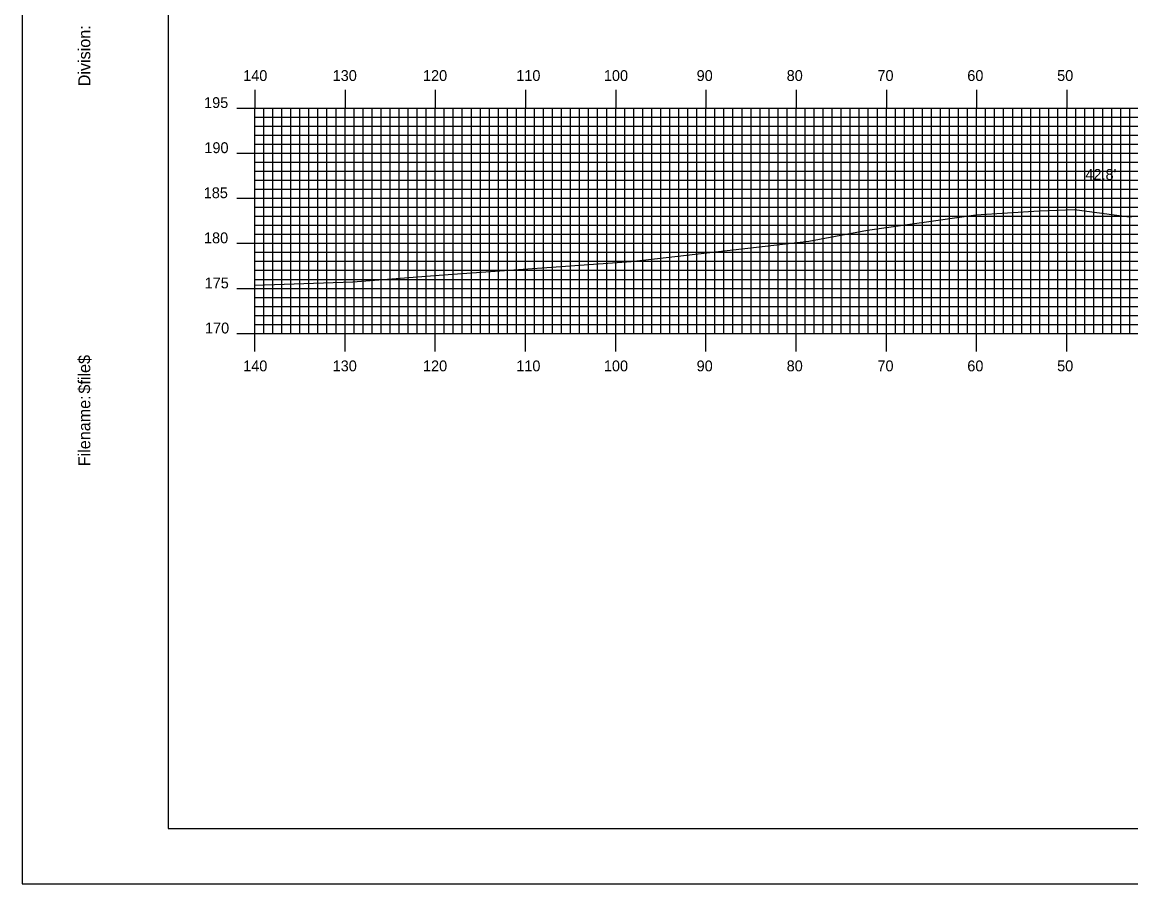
# Model space of a CAD drawing. Extents: x 1823966 to 1824309, y 442591 to 442811.
# Drawn here: x 1823966 to 1824088.9, y 442590.5 to 442686.1 of the extents above; entities that cross this region are included whole.
import ezdxf

# ---------------------------------------------------------------- set-up
doc = ezdxf.new("R2010")
doc.units = 0
for name, color, linetype in [('BORDER', 7, 'Continuous'), ('D_Text_Standard', 7, 'Continuous'), ('H_V ANNOTATION', 7, 'Continuous'), ('MAJOR', 7, 'Continuous'), ('MINOR', 7, 'Continuous'), ('PLOT BOUNDARY', 7, 'Continuous'), ('S_Roadway_Centerline', 7, 'Continuous')]:
    doc.layers.add(name, color=color, linetype=linetype)

msp = doc.modelspace()

# ---------------------------------------------------------------- linework, layer by layer
at = {"layer": 'BORDER'}
msp.add_lwpolyline([(1823982.22, 442596.67), (1824302.22, 442596.67), (1824302.22, 442806.67), (1823982.22, 442806.67)], close=True, dxfattribs=at)
at = {"layer": 'MAJOR'}
for p, q in [((1823991.82, 442678.59), (1823991.82, 442676.59)), ((1824001.82, 442678.59), (1824001.82, 442676.59)), ((1824011.82, 442678.59), (1824011.82, 442676.59)), ((1824021.82, 442678.59), (1824021.82, 442676.59)), ((1824031.82, 442678.59), (1824031.82, 442676.59)), ((1824041.82, 442678.59), (1824041.82, 442676.59)), ((1824051.82, 442678.59), (1824051.82, 442676.59)), ((1824061.82, 442678.59), (1824061.82, 442676.59)), ((1824071.82, 442678.59), (1824071.82, 442676.59)), ((1824081.82, 442678.59), (1824081.82, 442676.59)), ((1823989.82, 442676.59), (1823991.82, 442676.59)), ((1823991.82, 442676.59), (1824271.82, 442676.59)), ((1823991.82, 442651.59), (1823991.82, 442676.59)), ((1823991.82, 442651.59), (1823991.82, 442676.59)), ((1823991.82, 442676.59), (1824271.82, 442676.59)), ((1824001.82, 442651.59), (1824001.82, 442676.59)), ((1824011.82, 442651.59), (1824011.82, 442676.59)), ((1824021.82, 442651.59), (1824021.82, 442676.59)), ((1824031.82, 442651.59), (1824031.82, 442676.59)), ((1824041.82, 442651.59), (1824041.82, 442676.59)), ((1824051.82, 442651.59), (1824051.82, 442676.59)), ((1824061.82, 442651.59), (1824061.82, 442676.59)), ((1824071.82, 442651.59), (1824071.82, 442676.59)), ((1824081.82, 442651.59), (1824081.82, 442676.59)), ((1823989.82, 442671.59), (1823991.82, 442671.59)), ((1823991.82, 442671.59), (1824271.82, 442671.59)), ((1823989.82, 442666.59), (1823991.82, 442666.59)), ((1823991.82, 442666.59), (1824271.82, 442666.59)), ((1823989.82, 442661.59), (1823991.82, 442661.59)), ((1823991.82, 442661.59), (1824271.82, 442661.59)), ((1823989.82, 442656.59), (1823991.82, 442656.59)), ((1823991.82, 442656.59), (1824271.82, 442656.59)), ((1823989.82, 442651.59), (1823991.82, 442651.59)), ((1823991.82, 442651.59), (1824271.82, 442651.59)), ((1823991.82, 442651.59), (1824271.82, 442651.59)), ((1823991.82, 442649.58), (1823991.82, 442651.59)), ((1824001.82, 442649.58), (1824001.82, 442651.59)), ((1824011.82, 442649.58), (1824011.82, 442651.59)), ((1824021.82, 442649.58), (1824021.82, 442651.59)), ((1824031.82, 442649.58), (1824031.82, 442651.59)), ((1824041.82, 442649.58), (1824041.82, 442651.59)), ((1824051.82, 442649.58), (1824051.82, 442651.59)), ((1824061.82, 442649.58), (1824061.82, 442651.59)), ((1824071.82, 442649.58), (1824071.82, 442651.59)), ((1824081.82, 442649.58), (1824081.82, 442651.59))]:
    msp.add_line(p, q, dxfattribs=at)
at = {"layer": 'MINOR'}
for p, q in [((1823992.82, 442651.59), (1823992.82, 442676.59)), ((1823993.82, 442651.59), (1823993.82, 442676.59)), ((1823994.82, 442651.59), (1823994.82, 442676.59)), ((1823995.82, 442651.59), (1823995.82, 442676.59)), ((1823996.82, 442651.59), (1823996.82, 442676.59)), ((1823997.82, 442651.59), (1823997.82, 442676.59)), ((1823998.82, 442651.59), (1823998.82, 442676.59)), ((1823999.82, 442651.59), (1823999.82, 442676.59)), ((1824000.82, 442651.59), (1824000.82, 442676.59)), ((1824002.82, 442651.59), (1824002.82, 442676.59)), ((1824003.82, 442651.59), (1824003.82, 442676.59)), ((1824004.82, 442651.59), (1824004.82, 442676.59)), ((1824005.82, 442651.59), (1824005.82, 442676.59)), ((1824006.82, 442651.59), (1824006.82, 442676.59)), ((1824007.82, 442651.59), (1824007.82, 442676.59)), ((1824008.82, 442651.59), (1824008.82, 442676.59)), ((1824009.82, 442651.59), (1824009.82, 442676.59)), ((1824010.82, 442651.59), (1824010.82, 442676.59)), ((1824012.82, 442651.59), (1824012.82, 442676.59)), ((1824013.82, 442651.59), (1824013.82, 442676.59)), ((1824014.82, 442651.59), (1824014.82, 442676.59)), ((1824015.82, 442651.59), (1824015.82, 442676.59)), ((1824016.82, 442651.59), (1824016.82, 442676.59)), ((1824017.82, 442651.59), (1824017.82, 442676.59)), ((1824018.82, 442651.59), (1824018.82, 442676.59)), ((1824019.82, 442651.59), (1824019.82, 442676.59)), ((1824020.82, 442651.59), (1824020.82, 442676.59)), ((1824022.82, 442651.59), (1824022.82, 442676.59)), ((1824023.82, 442651.59), (1824023.82, 442676.59)), ((1824024.82, 442651.59), (1824024.82, 442676.59)), ((1824025.82, 442651.59), (1824025.82, 442676.59)), ((1824026.82, 442651.59), (1824026.82, 442676.59)), ((1824027.82, 442651.59), (1824027.82, 442676.59)), ((1824028.82, 442651.59), (1824028.82, 442676.59)), ((1824029.82, 442651.59), (1824029.82, 442676.59)), ((1824030.82, 442651.59), (1824030.82, 442676.59)), ((1824032.82, 442651.59), (1824032.82, 442676.59)), ((1824033.82, 442651.59), (1824033.82, 442676.59)), ((1824034.82, 442651.59), (1824034.82, 442676.59)), ((1824035.82, 442651.59), (1824035.82, 442676.59)), ((1824036.82, 442651.59), (1824036.82, 442676.59)), ((1824037.82, 442651.59), (1824037.82, 442676.59)), ((1824038.82, 442651.59), (1824038.82, 442676.59)), ((1824039.82, 442651.59), (1824039.82, 442676.59)), ((1824040.82, 442651.59), (1824040.82, 442676.59)), ((1824042.82, 442651.59), (1824042.82, 442676.59)), ((1824043.82, 442651.59), (1824043.82, 442676.59)), ((1824044.82, 442651.59), (1824044.82, 442676.59)), ((1824045.82, 442651.59), (1824045.82, 442676.59)), ((1824046.82, 442651.59), (1824046.82, 442676.59)), ((1824047.82, 442651.59), (1824047.82, 442676.59)), ((1824048.82, 442651.59), (1824048.82, 442676.59)), ((1824049.82, 442651.59), (1824049.82, 442676.59)), ((1824050.82, 442651.59), (1824050.82, 442676.59)), ((1824052.82, 442651.59), (1824052.82, 442676.59)), ((1824053.82, 442651.59), (1824053.82, 442676.59)), ((1824054.82, 442651.59), (1824054.82, 442676.59)), ((1824055.82, 442651.59), (1824055.82, 442676.59)), ((1824056.82, 442651.59), (1824056.82, 442676.59)), ((1824057.82, 442651.59), (1824057.82, 442676.59)), ((1824058.82, 442651.59), (1824058.82, 442676.59)), ((1824059.82, 442651.59), (1824059.82, 442676.59)), ((1824060.82, 442651.59), (1824060.82, 442676.59)), ((1824062.82, 442651.59), (1824062.82, 442676.59)), ((1824063.82, 442651.59), (1824063.82, 442676.59)), ((1824064.82, 442651.59), (1824064.82, 442676.59)), ((1824065.82, 442651.59), (1824065.82, 442676.59)), ((1824066.82, 442651.59), (1824066.82, 442676.59)), ((1824067.82, 442651.59), (1824067.82, 442676.59)), ((1824068.82, 442651.59), (1824068.82, 442676.59)), ((1824069.82, 442651.59), (1824069.82, 442676.59)), ((1824070.82, 442651.59), (1824070.82, 442676.59)), ((1824072.82, 442651.59), (1824072.82, 442676.59)), ((1824073.82, 442651.59), (1824073.82, 442676.59)), ((1824074.82, 442651.59), (1824074.82, 442676.59)), ((1824075.82, 442651.59), (1824075.82, 442676.59)), ((1824076.82, 442651.59), (1824076.82, 442676.59)), ((1824077.82, 442651.59), (1824077.82, 442676.59)), ((1824078.82, 442651.59), (1824078.82, 442676.59)), ((1824079.82, 442651.59), (1824079.82, 442676.59)), ((1824080.82, 442651.59), (1824080.82, 442676.59)), ((1824082.82, 442651.59), (1824082.82, 442676.59)), ((1824083.82, 442651.59), (1824083.82, 442676.59)), ((1824084.82, 442651.59), (1824084.82, 442676.59)), ((1824085.82, 442651.59), (1824085.82, 442676.59)), ((1824086.82, 442651.59), (1824086.82, 442676.59)), ((1824087.82, 442651.59), (1824087.82, 442676.59)), ((1824088.82, 442651.59), (1824088.82, 442676.59)), ((1823991.82, 442675.59), (1824271.82, 442675.59)), ((1823991.82, 442675.59), (1823993.83, 442675.59)), ((1823991.82, 442674.59), (1824271.82, 442674.59)), ((1823991.82, 442674.59), (1823993.83, 442674.59)), ((1823991.82, 442673.59), (1824271.82, 442673.59)), ((1823991.82, 442673.59), (1823993.83, 442673.59)), ((1823991.82, 442672.59), (1824271.82, 442672.59)), ((1823991.82, 442672.59), (1823993.83, 442672.59)), ((1823991.82, 442670.59), (1824271.82, 442670.59)), ((1823991.82, 442670.59), (1823993.83, 442670.59)), ((1823991.82, 442669.59), (1824271.82, 442669.59)), ((1823991.82, 442669.59), (1823993.83, 442669.59)), ((1823991.82, 442668.59), (1824271.82, 442668.59)), ((1823991.82, 442668.59), (1823993.83, 442668.59)), ((1823991.82, 442667.59), (1824271.82, 442667.59)), ((1823991.82, 442667.59), (1823993.83, 442667.59)), ((1823991.82, 442665.59), (1824271.82, 442665.59)), ((1823991.82, 442665.59), (1823993.83, 442665.59)), ((1823991.82, 442664.59), (1824271.82, 442664.59)), ((1823991.82, 442664.59), (1823993.83, 442664.59)), ((1823991.82, 442663.59), (1824271.82, 442663.59)), ((1823991.82, 442663.59), (1823993.83, 442663.59)), ((1823991.82, 442662.59), (1824271.82, 442662.59)), ((1823991.82, 442662.59), (1823993.83, 442662.59)), ((1823991.82, 442660.59), (1824271.82, 442660.59)), ((1823991.82, 442660.59), (1823993.83, 442660.59)), ((1823991.82, 442659.59), (1824271.82, 442659.59)), ((1823991.82, 442659.59), (1823993.83, 442659.59)), ((1823991.82, 442658.59), (1824271.82, 442658.59)), ((1823991.82, 442658.59), (1823993.83, 442658.59)), ((1823991.82, 442657.59), (1824271.82, 442657.59)), ((1823991.82, 442657.59), (1823993.83, 442657.59)), ((1823991.82, 442655.59), (1824271.82, 442655.59)), ((1823991.82, 442655.59), (1823993.83, 442655.59)), ((1823991.82, 442654.59), (1824271.82, 442654.59)), ((1823991.82, 442654.59), (1823993.83, 442654.59)), ((1823991.82, 442653.59), (1824271.82, 442653.59)), ((1823991.82, 442653.59), (1823993.83, 442653.59)), ((1823991.82, 442652.59), (1824271.82, 442652.59)), ((1823991.82, 442652.59), (1823993.83, 442652.59))]:
    msp.add_line(p, q, dxfattribs=at)
at = {"layer": 'PLOT BOUNDARY'}
msp.add_lwpolyline([(1823966.04, 442590.55), (1824306.04, 442590.55), (1824306.04, 442810.55), (1823966.04, 442810.55)], close=True, dxfattribs=at)
at = {"layer": 'S_Roadway_Centerline'}
msp.add_lwpolyline([(1823991.82, 442656.95), (1824002.69, 442657.31), (1824012.74, 442658.09), (1824033.52, 442659.56), (1824053.21, 442661.83), (1824059.73, 442663.03), (1824071.73, 442664.73), (1824078.76, 442665.19), (1824082.66, 442665.35), (1824088.74, 442664.54), (1824089.01, 442664.55)], dxfattribs=at)

# ---------------------------------------------------------------- texts
at = {"layer": 'BORDER'}
for s, p in [('Division:', (1823973.59, 442679)), ('$file$', (1823973.59, 442644.92)), ('Filename:', (1823973.59, 442636.86))]:
    msp.add_text(s, height=1.339, rotation=90, dxfattribs=at).set_placement(p)
at = {"layer": 'D_Text_Standard'}
msp.add_text("42.8'", height=1.2, dxfattribs=at).set_placement((1824083.88, 442668.62))
at = {"layer": 'H_V ANNOTATION'}
for s, p in [('140', (1823990.53, 442679.59)), ('130', (1824000.45, 442679.59)), ('120', (1824010.46, 442679.59)), ('110', (1824020.8, 442679.59)), ('100', (1824030.51, 442679.59)), ('90', (1824040.79, 442679.59)), ('80', (1824050.77, 442679.59)), ('70', (1824060.83, 442679.59)), ('60', (1824070.79, 442679.59)), ('50', (1824080.75, 442679.59)), ('195', (1823986.2, 442676.59)), ('190', (1823986.23, 442671.59)), ('185', (1823986.16, 442666.59)), ('180', (1823986.19, 442661.59)), ('175', (1823986.26, 442656.59)), ('170', (1823986.3, 442651.59)), ('140', (1823990.53, 442647.39)), ('130', (1824000.45, 442647.39)), ('120', (1824010.46, 442647.39)), ('110', (1824020.8, 442647.39)), ('100', (1824030.51, 442647.39)), ('90', (1824040.79, 442647.39)), ('80', (1824050.77, 442647.39)), ('70', (1824060.83, 442647.39)), ('60', (1824070.79, 442647.39)), ('50', (1824080.75, 442647.39))]:
    msp.add_text(s, height=1.2, dxfattribs=at).set_placement(p)
at = {"layer": 'MAJOR'}
msp.add_text('-', height=0.012, dxfattribs=at).set_placement((1823991.81, 442651.59))

doc.saveas('drawing.dxf')
